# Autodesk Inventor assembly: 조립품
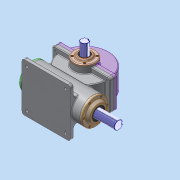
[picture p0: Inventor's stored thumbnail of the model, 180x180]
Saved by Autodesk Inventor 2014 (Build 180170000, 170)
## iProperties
Created: 2023-12
Part Number: 조립품
Document SubType Name: Assembly
Designer: dg
Mass: 21922 g
Surface Area: 7843.92 cm^2
Volume: 4928.8 cm^3
Author: dg
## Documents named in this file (14)
- C:\Users\dg\Desktop\631208V1006\조립품.iam
- C:\Users\dg\Desktop\631208V1006\본체.ipt
- C:\Users\dg\Desktop\631208V1006\깊은 홈 볼 베어링 6209.ipt
- C:\Users\dg\Desktop\631208V1006\뒤커버.ipt
- C:\Users\dg\Desktop\631208V1006\앞커버.ipt
- C:\Users\dg\Desktop\631208V1006\오일 실 35 55 11.ipt
- C:\Users\dg\Desktop\631208V1006\웜 샤프트.ipt
- C:\Users\dg\Desktop\631208V1006\깊은 홈 볼 베어링 6206.ipt
- C:\Users\dg\Desktop\631208V1006\서브커버.ipt
- C:\Users\dg\Desktop\631208V1006\오일 실 30 42 7.ipt
- C:\Users\dg\Desktop\631208V1006\웜 휠.ipt
- C:\Users\dg\Desktop\631208V1006\본체 커버.ipt
- C:\Users\dg\Desktop\631208V1006\육각 소켓 머리 볼트 M5 x 12.ipt
- C:\Users\dg\Desktop\631208V1006\육각 소켓 머리 볼트 M6 x 20.ipt
